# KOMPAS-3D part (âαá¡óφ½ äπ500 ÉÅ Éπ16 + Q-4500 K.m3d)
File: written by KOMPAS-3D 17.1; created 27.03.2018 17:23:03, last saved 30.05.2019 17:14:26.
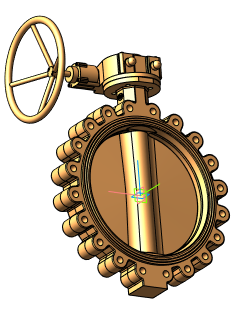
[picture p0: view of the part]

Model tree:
1. Операция без истории:7  (labels: Сталь 20  ГОСТ 1050-2013)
